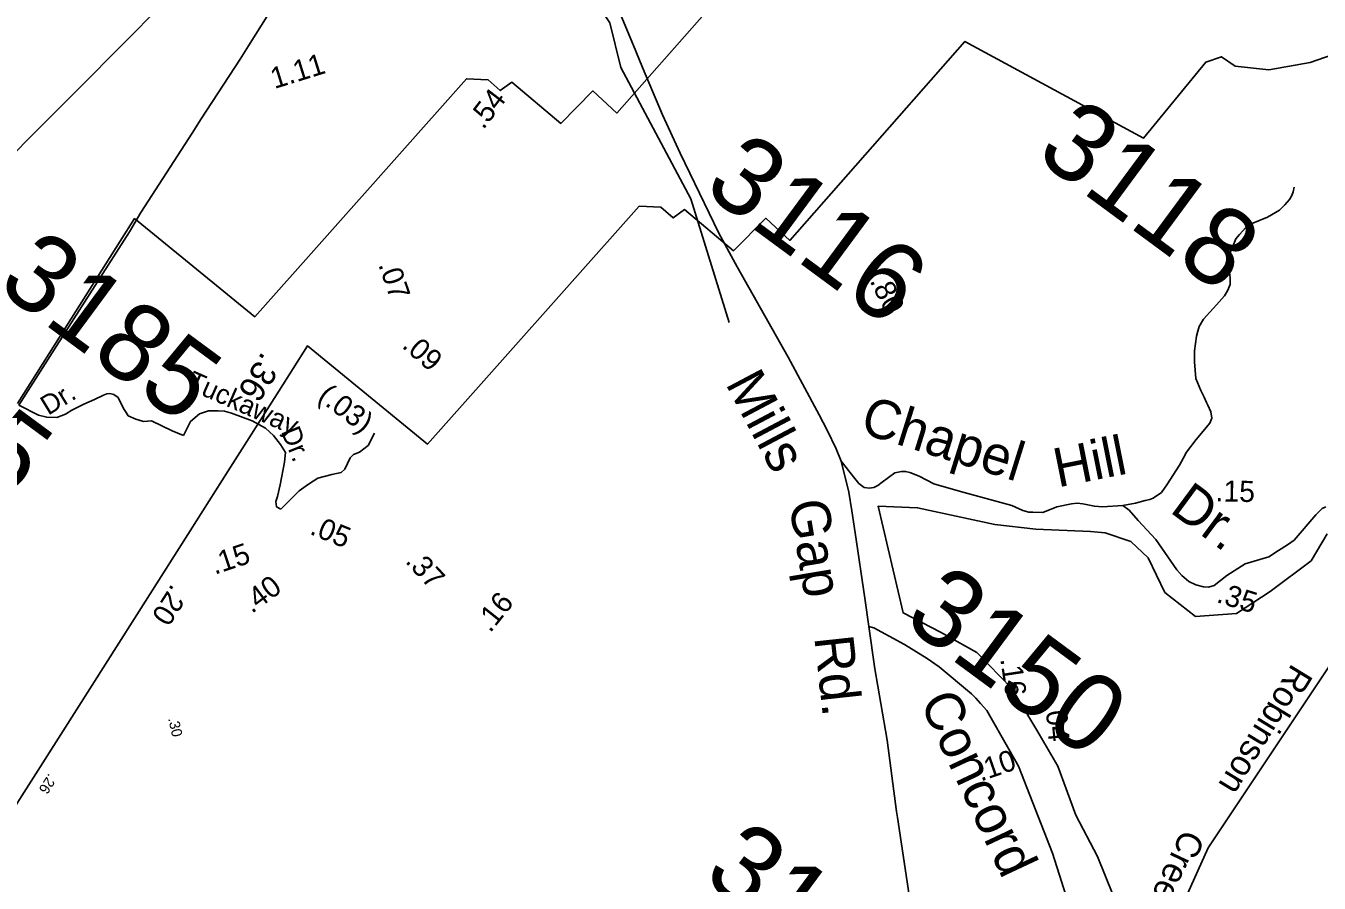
# Model space of a CAD drawing. Extents: x 945666 to 965748, y 644452 to 663300.
# Drawn here: x 953745 to 954740, y 658587 to 659246 of the extents above; entities that cross this region are included whole.
import ezdxf

# ---------------------------------------------------------------- set-up
doc = ezdxf.new("R2010")
doc.units = 0
for name, color, linetype in [('Default', 7, 'Continuous'), ('Exist Boundary Political City Limit New', 7, 'Continuous'), ('Exist Boundary Political Urban Extension UEB', 7, 'Continuous'), ('Exist Hydrographic Creek Single Shore', 7, 'Continuous'), ('Exist Railroad Mainline', 7, 'Continuous'), ('Exist Road Primary US Mileage Hundredths English Label', 7, 'Continuous'), ('Exist Road Primary US UnDivided 4 Lane Attributed', 7, 'Continuous'), ('Exist Road Secondary Mileage Tenths English Label', 7, 'Continuous'), ('Exist Road Secondary Type 51 Attributed', 7, 'Continuous'), ('Exist Road Secondary Type 51 Label', 7, 'Continuous'), ('Old_Level_1', 7, 'Continuous'), ('Old_Level_28', 7, 'Continuous'), ('Prop Paved Shoulder', 7, 'Continuous'), ('Sheet Sticker Preliminary CELL', 7, 'Continuous')]:
    doc.layers.add(name, color=color, linetype=linetype)

msp = doc.modelspace()

# ---------------------------------------------------------------- linework, layer by layer
at = {"layer": 'Default'}
for points in [[(954137.42, 659406.62), (954167.04, 659340.74), (954214.25, 659226.89), (954219.17, 659214.5), (954234.76, 659177.83), (954248.16, 659148.39), (954278.06, 659087), (954292.16, 659061.01), (954331.21, 658991.49), (954355.24, 658946.97), (954361.3, 658935.37), (954368.18, 658920.76), (954371.98, 658911.32)], [(954371.98, 658911.32), (954378, 658887.65), (954380.2, 658873.1), (954382.91, 658856.22), (954390.37, 658806.01)], [(954393.48, 658784.22), (954398, 658751.55), (954402.51, 658724.78), (954407.51, 658696.55), (954414.71, 658641.7), (954415.47, 658637.26), (954430.43, 658536.29)]]:
    msp.add_lwpolyline(points, dxfattribs=at)
at = {"layer": 'Exist Boundary Political City Limit New'}
msp.add_lwpolyline([(954764.84, 659416.94), (954738.12, 659386.29), (954703.48, 659345.2), (954669.25, 659340.27), (954599.91, 659316.21), (954568.17, 659310.66), (954542.24, 659313.52), (954531.6, 659320.72), (954519.65, 659316.53), (954471.84, 659258.02), (954334.37, 659332.51), (954199.61, 659179.31), (954181.17, 659196.36), (954156.43, 659171.36), (954118.74, 659203), (954109.85, 659196.66), (954100.54, 659204.87), (954083.83, 659205.72), (953921.01, 659022.58), (953828.63, 659098.16), (953806.55, 659063.26), (953767.75, 659001.98), (953738.57, 658955.88)], dxfattribs=at)
at = {"layer": 'Exist Boundary Political Urban Extension UEB'}
msp.add_lwpolyline([(954745.87, 658855.37), (954733.59, 658834.74), (954701.99, 658811), (954676.25, 658794.08), (954644.62, 658791.76), (954621.06, 658810.42), (954608.21, 658837.01), (954594.8, 658849.63), (954575.15, 658856.23), (954563.95, 658857.14), (954521.82, 658859.15), (954490.33, 658862.7), (954430.85, 658875.48), (954400.47, 658876.64), (954419.85, 658794.62), (954448.5, 658779.9), (954476.42, 658764.25), (954503.27, 658736.52), (954522.6, 658704.29), (954538.62, 658676.68), (954552.52, 658638.81), (954569.29, 658607.11), (954581.06, 658577.89)], dxfattribs=at)
at = {"layer": 'Exist Hydrographic Creek Single Shore'}
for points in [[(954285.98, 659018.04), (954256.55, 659113.26), (954202.7, 659214.34), (954194.18, 659248.85), (954164.42, 659293.23), (954116.6, 659339.14), (954109.6, 659354.74), (954101.67, 659388.26), (954082.77, 659425.37), (954039.54, 659473.66), (954033.02, 659491.57), (954028.3, 659515.14), (954024.39, 659569.26), (954026.31, 659583.85)], [(954421.51, 658112.44), (954444.46, 658163.91), (954453.2, 658188.91), (954457.41, 658230.84), (954466.63, 658251.17), (954526.07, 658336.65), (954530.85, 658356.63), (954524.16, 658393.5), (954531.99, 658420.82), (954541.65, 658436.51), (954567.79, 658457.27), (954573.54, 658466.29), (954575.42, 658496.56), (954594.67, 658522.62), (954601.49, 658525.99), (954630.4, 658560.75), (954654.47, 658613.75), (954748.12, 658754.64), (954752.92, 658781.6), (954757.22, 658835.82), (954778.6, 658878.53), (954800.25, 658928.48), (954819.84, 658956.5)]]:
    msp.add_lwpolyline(points, dxfattribs=at)
at = {"layer": 'Exist Railroad Mainline'}
msp.add_lwpolyline([(954077.64, 659433.83), (954032.56, 659413.87), (954027.66, 659412.26), (954018.07, 659408.66), (954008.94, 659403.21), (954000.46, 659398.98), (953992.93, 659394.01), (953986.11, 659390.87), (953973.97, 659382.36), (953958.83, 659370.77), (953946.62, 659362.1), (953944.59, 659360.43), (953938.6, 659355.79), (953928.94, 659346.44), (953918.18, 659336.22), (953911.09, 659328.12), (953905.21, 659321.67), (953870.08, 659284.17), (953864.21, 659277.93), (953855.1, 659268.59), (953846.88, 659259.86), (953836.11, 659249.21), (953832.76, 659245.77), (953650.24, 659062.44)], dxfattribs=at)
at = {"layer": 'Exist Road Primary US UnDivided 4 Lane Attributed'}
for points in [[(953872.78, 659163.87), (953879.82, 659174.92), (953909.71, 659220.77), (953916.18, 659231.14), (953931.95, 659255.99), (953952.66, 659289.4), (953970.09, 659312.1), (953980.01, 659323.09), (953984.98, 659327.65), (953992.31, 659333.42), (954004.62, 659342.01), (954014.69, 659348.25), (954022.49, 659352.55), (954042.24, 659361.63), (954062.46, 659370.95), (954132.38, 659402.25), (954137.42, 659406.62)], [(953739.6, 658954.55), (953781.83, 659020.84), (953824.56, 659087.83), (953833.32, 659102.74), (953872.78, 659163.87)]]:
    msp.add_lwpolyline(points, dxfattribs=at)
at = {"layer": 'Exist Road Secondary Type 51 Attributed'}
msp.add_line((954390.37, 658806.01), (954393.48, 658784.22), dxfattribs=at)
for points in [[(954588.83, 658877.26), (954598.41, 658879.14), (954605.84, 658881.11), (954609.43, 658881.78), (954612.09, 658883.01), (954618.38, 658887.28), (954622.56, 658893.18), (954632.29, 658908.21), (954635.39, 658914.04), (954637.78, 658918.31), (954645.12, 658928.01), (954655.53, 658940.76), (954657.16, 658944.48), (954656.37, 658949.47), (954654.2, 658954.46), (954653.12, 658956.45), (954651.38, 658960.54), (954648.75, 658965.81), (954645, 658974.99), (954643.81, 658987.73), (954643.87, 658996.43), (954644.62, 659002.03), (954645.27, 659007.52), (954646.48, 659011.45), (954647.54, 659014.94), (954650.8, 659020.57), (954655.7, 659026.13), (954660.77, 659031.67), (954666.89, 659038.57), (954669.23, 659042.55), (954671.38, 659047.39), (954671.26, 659052.55), (954670.5, 659058.65), (954670.73, 659067.3), (954671.63, 659072.52), (954674.2, 659078.65), (954675.67, 659082.47), (954678.49, 659085.77), (954683.38, 659091.23), (954688.61, 659094.69), (954700.08, 659099.17), (954709.11, 659104.71), (954713.34, 659108.63), (954716.86, 659112.81), (954718.66, 659115.85), (954719.83, 659118.65), (954720.42, 659122.23)], [(953739.6, 658954.55), (953754.75, 658946.78), (953760.99, 658945.21), (953768.88, 658944.91), (953775.52, 658947.51), (953780.23, 658950.63), (953789.58, 658955.33), (953797.78, 658958.82), (953804.57, 658962.11), (953807.13, 658963.16), (953809.51, 658963.37), (953812.75, 658962.68), (953815.95, 658960.49), (953820.18, 658951.84), (953822.03, 658948.79), (953823.69, 658946.32)], [(953823.69, 658946.32), (953829.48, 658943.65), (953835.33, 658941.95), (953841.57, 658942.39), (953857.52, 658934.65), (953866.18, 658931.03)], [(953866.18, 658931.03), (953871.55, 658942.03), (953878.55, 658947.91), (953885.57, 658950.12), (953892.93, 658950.05), (953897.85, 658949.83), (953903.11, 658948.33), (953919.11, 658942.4), (953929.34, 658936.77), (953935.38, 658931.12), (953940.83, 658924.22), (953944.74, 658918.13), (953944.01, 658910.63), (953940.52, 658893.07), (953938.41, 658884.2), (953937.25, 658880.34), (953937.86, 658876.28), (953941.12, 658874.36)], [(953941.12, 658874.36), (953955.28, 658888.59), (953962.24, 658893.79), (953969.59, 658898.22), (953980.35, 658901.09), (953987.45, 658902.58), (953990.37, 658905.24), (953994.44, 658914.01), (953996.97, 658916.47), (954001.67, 658918.28), (954008.2, 658923.56), (954013.16, 658932.88)], [(954588.83, 658877.26), (954573.16, 658876.17), (954566.85, 658876.7), (954558.09, 658878.52), (954553.58, 658879.03), (954549.18, 658878.49), (954537.99, 658876.26), (954527.23, 658871.93), (954519.63, 658872.05), (954516.46, 658872.05), (954511.84, 658873.52), (954503.43, 658877.34), (954463.9, 658887.98), (954443.28, 658894.05), (954432.09, 658899.79), (954424.96, 658902.73), (954421.57, 658903.48), (954418.56, 658903.39), (954413.34, 658902.29), (954403.6, 658895.15), (954400.39, 658892.75), (954397.22, 658891.09), (954393.7, 658890.55), (954389.66, 658891.1), (954385.68, 658894.15), (954381.63, 658899.27), (954371.98, 658911.32)], [(954744.85, 658876.29), (954742.1, 658874.95), (954737.15, 658870.19), (954720.4, 658850.51), (954715.42, 658847.01), (954708.46, 658842.56), (954700.99, 658837.85), (954682.74, 658832.42), (954668.66, 658823.3), (954659, 658815.69), (954654.7, 658814.44), (954650.81, 658814.55), (954644.88, 658816.25), (954639.53, 658818.89), (954634.16, 658823.33), (954630.15, 658827.88), (954613.99, 658850.98), (954600.52, 658865.71), (954593.63, 658873.59), (954588.83, 658877.26)], [(954393.48, 658784.22), (954397.25, 658783.05), (954420.77, 658770.33), (954438.23, 658759.42), (954447.56, 658752.98), (954472.25, 658732.21), (954475.6, 658728.88), (954479.35, 658724.92), (954484.02, 658719.42), (954487.33, 658713.67), (954508.43, 658676.75), (954534.71, 658609.71), (954548.49, 658566.18), (954552.98, 658554.2), (954556.83, 658548.77), (954562.57, 658545.32), (954571.7, 658544.41), (954580.35, 658545.1), (954589.97, 658545.51), (954595.21, 658544.93)]]:
    msp.add_lwpolyline(points, dxfattribs=at)
at = {"layer": 'Old_Level_28'}
msp.add_lwpolyline([(954802.16, 659242.25), (954732.81, 659218.19), (954701.07, 659212.65), (954675.14, 659215.5), (954664.5, 659222.7), (954652.56, 659218.52), (954604.74, 659160), (954467.27, 659234.49), (954332.52, 659081.29), (954314.07, 659098.34), (954289.33, 659073.34), (954251.65, 659104.98), (954242.76, 659098.64), (954233.44, 659106.86), (954216.73, 659107.7), (954053.91, 658924.56), (953961.53, 659000.15), (953939.45, 658965.24), (953900.65, 658903.97), (953871.47, 658857.86), (953773.55, 658703.93), (953704.85, 658596.15)], dxfattribs=at)

# ---------------------------------------------------------------- texts
at = {"layer": 'Exist Road Primary US Mileage Hundredths English Label'}
for s, height, rotation, p in [('1.11', 16.238, 17.28006, (953936.14, 659197.78)), ('.54', 16.238, 52.48088, (954096.81, 659166.04)), ('.36', 19.486, 237.46825, (953926.97, 658996.36)), ('.20', 16.238, 237.5432, (953857.32, 658817.52)), ('.26', 8.119, 237.59706, (953762.63, 658671.48))]:
    msp.add_text(s, height=height, rotation=rotation, dxfattribs=at).set_placement(p)
at = {"layer": 'Exist Road Secondary Mileage Tenths English Label'}
for s, height, rotation, p in [('.07', 16.238, 289.17933, (954015.89, 659062.68)), ('.09', 16.238, 318.75709, (954033.55, 658999.4)), ('(.03)', 16.238, 322.95081, (953968.58, 658959.12)), ('.15', 16.238, 358.95236, (954660, 658880.46)), ('.05', 16.238, 337.64947, (953962.56, 658855.57)), ('.15', 16.238, 18.39622, (953890.2, 658823.95)), ('.37', 16.238, 312.6992, (954036.2, 658833.87)), ('.40', 16.238, 36.64808, (953918.77, 658793.68)), ('.35', 16.238, 342.63958, (954660.05, 658803.06)), ('.16', 16.238, 51.36022, (954102.11, 658778.76)), ('.16', 16.238, 278.59291, (954494.39, 658759.14)), ('.04', 16.238, 275.56466, (954528.92, 658724.97)), ('.30', 8.119, 282.7511, (953854.37, 658713.26)), ('.10', 16.238, 19.18534, (954479.51, 658664.72))]:
    msp.add_text(s, height=height, rotation=rotation, dxfattribs=at).set_placement(p)
at = {"layer": 'Exist Road Secondary Type 51 Label'}
for s, height, rotation, p in [('Tuckaway', 15, 336.1912, (953867.79, 658967.56)), ('Mills', 30, 297.90118, (954282.72, 658971.2)), ('Dr.', 15, 31.49447, (953762.15, 658946.3)), ('Chapel', 30, 342.63958, (954385.52, 658933.54)), ('Dr.', 15, 292.14689, (953940.95, 658934.34)), ('Hill', 30, 11.27114, (954538.74, 658891.11)), ('Dr.', 30, 323.59084, (954624.01, 658872.68)), ('Gap', 30, 279.4943, (954331.81, 658879.66)), ('Rd.', 30, 276.21974, (954351.36, 658775.91)), ('Concord', 30, 295.13218, (954432.18, 658726.11))]:
    msp.add_text(s, height=height, rotation=rotation, dxfattribs=at).set_placement(p)
at = {"layer": 'Old_Level_1'}
for s, p in [('3118', (954520.16, 659145.58)), ('3116', (954264.55, 659119.55)), ('3185', (953721.39, 659044.71)), ('3185', (953591.29, 658986.71)), ('3150', (954418.61, 658786.92)), ('3116', (954264.17, 658589.85))]:
    msp.add_text(s, height=60, rotation=323.59084, dxfattribs=at).set_placement(p)
at = {"layer": 'Prop Paved Shoulder'}
for s, rotation, p in [('Robinson', 238.54543, (954719.09, 658756.31)), ('Creek', 244.64993, (954634.84, 658629.06))]:
    msp.add_text(s, height=19.486, rotation=rotation, dxfattribs=at).set_placement(p)
at = {"layer": 'Sheet Sticker Preliminary CELL'}
msp.add_text('.80', height=16.238, rotation=295.96844, dxfattribs=at).set_placement((954393.79, 659050.21))

doc.saveas('drawing.dxf')
